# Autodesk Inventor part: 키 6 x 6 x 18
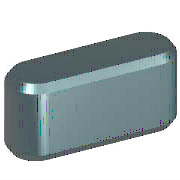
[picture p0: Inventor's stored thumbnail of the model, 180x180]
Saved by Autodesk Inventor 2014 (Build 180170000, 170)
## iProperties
Created: 2012-02
Part Number: 키 6 x 6 x 18
Material: 강철, 연강
Description: 키 및 해당 키홈
Document SubType Name: Modeling
Standard: KS B 1311
Designer: mduedu
Standards Organization: KS
Language: ko-KR
Size Designation: 6 x 6 x 18
Categories: <MemberInstance><Categories><Category DisplayName="샤프트 부품" InternalName="7f7aeb1f-a693-4053-b835-cee3144e0d98" Mnemonic="SHFT"><Category DisplayName="키" Interna
Density: 1 g/cm^3
Appearance: 노란색
IsCustomPart: 1
Author: mduedu
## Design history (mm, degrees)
workplane "Work Plane1"
workplane "Work Plane2"
sketch "스케치1"
  geometry: L1 (3, 3)-(15, 3); L2 (15, -3)-(3, -3); L3 (0, 9.4)-(0, -7.4) reference; L4 (-5, 0)-(30, 0) reference; L5 (18, 0)-(18, 7); A1 r 3 centre (3, 0) between (3, 3) and (3, -3); A2 r 3 centre (15, 0) between (15, -3) and (15, 3)
  constraints: 6 end point, 5 point on circle, 4 tangent, 3 point on line, 2 centre point, 1 horizontal, 1 parallel, 1 perpendicular
  dimensions: "d0" = 3 radius of A1 (= 0.5 x PB); "d13" = 3 radius of A2 (= 0.5 x PB); "d14" = 18 distance between parallel lines of L5 L3 (= NLG)
extrude "본체1" new body sketch "스케치1" taper "d3" = 0 deg; stored distance "d4" = 10
workplane "Work Plane3"
body "Solid1"
chamfer "모따기1" distance "d8" = 0.4 (= PHH); stored, may be unused: second distance "d9" = 0.4 (= PHH), angle "d15" = 45 deg
other parameters: "d1" = -3.5 (= -PNT), "d2" = 2.5 (= PH - PNT), "NLG" = 18 [user parameter; used in 3 equation terms], "PB" = 6 [user parameter; used in 2 equation terms], "PNT" = 3.5 [user parameter; used in 2 equation terms], "PH" = 6 [user parameter; used in 1 equation term], "PHH" = 0.4 [user parameter; used in 2 equation terms], "d10" = 0, "d16" = 0, "d17" = 0, "d18" = 0, "WDMIN" = 17 [user parameter], "PLB2" = 18 (= NLG) [user parameter], "WDMAX" = 22 [user parameter], "PLB1" = 18 (= NLG) [user parameter], "RR" = 0.16 [user parameter], "PUEB" = 2.8 [user parameter]
